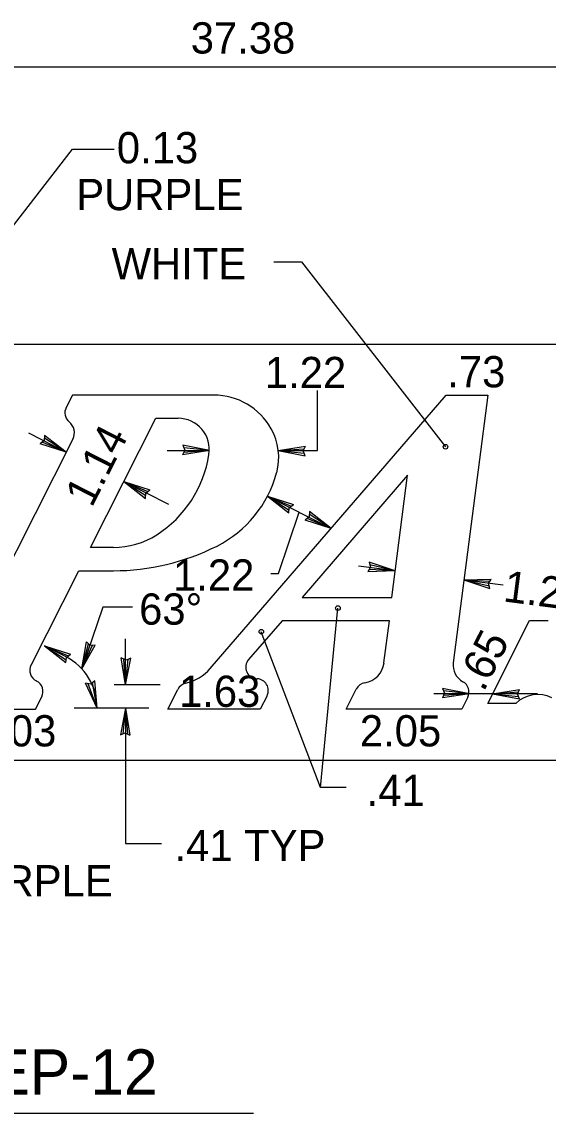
# Model space of a CAD drawing. Extents: x 10268197 to 10268826, y 2141503 to 2142677.
# Drawn here: x 10268799.84 to 10268809.85, y 2142357.53 to 2142378.29 of the extents above; entities that cross this region are included whole.
import ezdxf

# ---------------------------------------------------------------- set-up
doc = ezdxf.new("R2010")
doc.units = 0
for name, color, linetype in [('1', 7, 'Continuous'), ('21', 7, 'Continuous'), ('Default', 7, 'Continuous')]:
    doc.layers.add(name, color=color, linetype=linetype)

msp = doc.modelspace()

# ---------------------------------------------------------------- linework, layer by layer
at = {"layer": '1'}
for p, q in [((10268783.958, 2142377.436), (10268805.311, 2142377.436)), ((10268805.311, 2142377.436), (10268824.378, 2142377.436)), ((10268799.078, 2142373.645), (10268800.798, 2142375.868)), ((10268800.798, 2142375.868), (10268801.593, 2142375.868)), ((10268804.629, 2142373.722), (10268805.152, 2142373.722)), ((10268805.152, 2142373.722), (10268807.892, 2142370.208)), ((10268805.46, 2142370.136), (10268805.46, 2142371.278)), ((10268799.961, 2142370.47), (10268800.679, 2142370.104)), ((10268800.269, 2142370.424), (10268800.261, 2142370.326)), ((10268800.679, 2142370.104), (10268800.269, 2142370.424)), ((10268800.261, 2142370.326), (10268800.184, 2142370.264)), ((10268800.679, 2142370.104), (10268800.184, 2142370.264)), ((10268800.679, 2142370.104), (10268800.225, 2142370.297)), ((10268800.679, 2142370.104), (10268800.264, 2142370.373)), ((10268803.405, 2142370.136), (10268802.894, 2142370.235)), ((10268802.894, 2142370.235), (10268802.932, 2142370.144)), ((10268803.405, 2142370.136), (10268802.914, 2142370.187)), ((10268804.712, 2142370.136), (10268805.227, 2142370.217)), ((10268805.186, 2142370.128), (10268805.227, 2142370.217)), ((10268802.598, 2142370.136), (10268803.405, 2142370.136)), ((10268802.932, 2142370.144), (10268802.891, 2142370.054)), ((10268803.405, 2142370.136), (10268802.891, 2142370.054)), ((10268803.405, 2142370.136), (10268802.912, 2142370.101)), ((10268804.712, 2142370.136), (10268805.205, 2142370.17)), ((10268804.712, 2142370.136), (10268805.46, 2142370.136)), ((10268804.712, 2142370.136), (10268805.223, 2142370.037)), ((10268804.712, 2142370.136), (10268805.204, 2142370.085)), ((10268805.223, 2142370.037), (10268805.186, 2142370.128)), ((10268801.777, 2142369.546), (10268802.623, 2142369.114)), ((10268801.777, 2142369.546), (10268802.272, 2142369.385)), ((10268801.777, 2142369.546), (10268802.187, 2142369.225)), ((10268801.777, 2142369.546), (10268802.191, 2142369.277)), ((10268801.777, 2142369.546), (10268802.231, 2142369.353)), ((10268802.194, 2142369.324), (10268802.272, 2142369.385)), ((10268802.187, 2142369.225), (10268802.194, 2142369.324)), ((10268804.505, 2142369.27), (10268805.717, 2142368.652)), ((10268804.505, 2142369.27), (10268804.999, 2142369.109)), ((10268804.505, 2142369.27), (10268804.915, 2142368.95)), ((10268804.505, 2142369.27), (10268804.919, 2142369.002)), ((10268804.505, 2142369.27), (10268804.958, 2142369.077)), ((10268804.915, 2142368.95), (10268804.922, 2142369.048)), ((10268804.922, 2142369.048), (10268804.999, 2142369.109)), ((10268806.937, 2142367.846), (10268806.239, 2142367.937)), ((10268806.468, 2142367.915), (10268806.416, 2142367.831)), ((10268806.937, 2142367.846), (10268806.443, 2142368.01)), ((10268806.443, 2142368.01), (10268806.468, 2142367.915)), ((10268806.937, 2142367.846), (10268806.456, 2142367.96)), ((10268806.937, 2142367.846), (10268806.416, 2142367.831)), ((10268806.937, 2142367.846), (10268806.444, 2142367.875)), ((10268808.244, 2142367.677), (10268808.764, 2142367.691)), ((10268808.244, 2142367.677), (10268808.989, 2142367.58)), ((10268808.244, 2142367.677), (10268808.737, 2142367.512)), ((10268808.244, 2142367.677), (10268808.725, 2142367.563)), ((10268808.244, 2142367.677), (10268808.736, 2142367.648)), ((10268808.712, 2142367.608), (10268808.764, 2142367.691)), ((10268808.737, 2142367.512), (10268808.712, 2142367.608)), ((10268801.373, 2142367.159), (10268800.975, 2142365.984)), ((10268801.938, 2142367.159), (10268801.373, 2142367.159)), ((10268805.518, 2142363.728), (10268805.846, 2142367.139)), ((10268805.518, 2142363.728), (10268804.39, 2142366.69)), ((10268800.975, 2142365.984), (10268801.063, 2142366.496)), ((10268800.975, 2142365.984), (10268801.101, 2142366.461)), ((10268801.135, 2142366.429), (10268801.063, 2142366.496)), ((10268801.809, 2142365.676), (10268801.809, 2142366.555)), ((10268800.668, 2142366.215), (10268800.264, 2142366.422)), ((10268800.264, 2142366.422), (10268800.759, 2142366.26)), ((10268800.264, 2142366.422), (10268800.674, 2142366.101)), ((10268800.264, 2142366.422), (10268800.678, 2142366.153)), ((10268800.264, 2142366.422), (10268800.718, 2142366.229)), ((10268800.682, 2142366.199), (10268800.759, 2142366.26)), ((10268800.975, 2142365.984), (10268801.233, 2142366.435)), ((10268800.975, 2142365.984), (10268801.182, 2142366.432)), ((10268801.233, 2142366.435), (10268801.135, 2142366.429)), ((10268800.674, 2142366.101), (10268800.682, 2142366.199)), ((10268801.809, 2142365.676), (10268801.727, 2142366.19)), ((10268801.817, 2142366.15), (10268801.727, 2142366.19)), ((10268801.809, 2142365.676), (10268801.774, 2142366.168)), ((10268801.809, 2142365.676), (10268801.908, 2142366.187)), ((10268801.809, 2142365.676), (10268801.86, 2142366.167)), ((10268801.908, 2142366.187), (10268801.817, 2142366.15)), ((10268801.268, 2142365.237), (10268801.048, 2142365.709)), ((10268801.145, 2142365.694), (10268801.048, 2142365.709)), ((10268801.268, 2142365.237), (10268801.099, 2142365.701)), ((10268801.223, 2142365.755), (10268801.145, 2142365.694)), ((10268801.268, 2142365.237), (10268801.182, 2142365.723)), ((10268801.268, 2142365.237), (10268801.223, 2142365.755)), ((10268802.468, 2142365.676), (10268801.589, 2142365.676)), ((10268808.349, 2142365.511), (10268807.673, 2142365.511)), ((10268808.788, 2142365.511), (10268808.349, 2142365.511)), ((10268809.645, 2142365.511), (10268808.788, 2142365.511)), ((10268802.248, 2142365.237), (10268800.829, 2142365.237)), ((10268801.809, 2142365.237), (10268801.709, 2142364.726)), ((10268801.809, 2142365.237), (10268801.757, 2142364.746)), ((10268801.809, 2142365.237), (10268801.809, 2142362.659)), ((10268801.809, 2142365.237), (10268801.89, 2142364.723)), ((10268801.809, 2142365.237), (10268801.843, 2142364.745)), ((10268801.709, 2142364.726), (10268801.801, 2142364.764)), ((10268801.801, 2142364.764), (10268801.89, 2142364.723)), ((10268806.004, 2142363.728), (10268805.518, 2142363.728)), ((10268801.809, 2142362.659), (10268802.494, 2142362.659))]:
    msp.add_line(p, q, dxfattribs=at)
msp.add_lwpolyline([(10268804.569, 2142367.794), (10268804.717, 2142367.794), (10268805.111, 2142368.961)], dxfattribs=at)
for centre in [(10268807.892, 2142370.208), (10268805.846, 2142367.139), (10268804.39, 2142366.69)]:
    msp.add_circle(centre, 0.0439, dxfattribs=at)
msp.add_arc((10268800.169, 2142365.237), 1.098, 0, 62.9941, dxfattribs=at)
at = {"layer": '21'}
for p, q in [((10268805.306, 2142368.973), (10268805.298, 2142368.875)), ((10268805.717, 2142368.652), (10268805.306, 2142368.973)), ((10268805.298, 2142368.875), (10268805.221, 2142368.813)), ((10268805.717, 2142368.652), (10268805.221, 2142368.813)), ((10268805.717, 2142368.652), (10268805.262, 2142368.845)), ((10268805.717, 2142368.652), (10268805.302, 2142368.922)), ((10268807.875, 2142365.519), (10268807.834, 2142365.43)), ((10268808.349, 2142365.511), (10268807.834, 2142365.43)), ((10268808.349, 2142365.511), (10268807.838, 2142365.61)), ((10268807.838, 2142365.61), (10268807.875, 2142365.519)), ((10268808.349, 2142365.511), (10268807.856, 2142365.477)), ((10268808.349, 2142365.511), (10268807.857, 2142365.562)), ((10268808.788, 2142365.511), (10268809.303, 2142365.593)), ((10268808.788, 2142365.511), (10268809.281, 2142365.546)), ((10268808.788, 2142365.511), (10268809.3, 2142365.412)), ((10268808.788, 2142365.511), (10268809.28, 2142365.46)), ((10268809.262, 2142365.503), (10268809.303, 2142365.593)), ((10268809.3, 2142365.412), (10268809.262, 2142365.503)), ((10268794.399, 2142357.533), (10268804.24, 2142357.533))]:
    msp.add_line(p, q, dxfattribs=at)
at = {"layer": 'Default'}
for p, q in [((10268799.315, 2142372.157), (10268824.378, 2142372.157)), ((10268800.797, 2142371.19), (10268800.678, 2142370.954)), ((10268803.488, 2142371.19), (10268800.797, 2142371.19)), ((10268803.42, 2142365.991), (10268807.907, 2142371.19)), ((10268807.907, 2142371.19), (10268808.698, 2142371.19)), ((10268808.698, 2142371.19), (10268808.04, 2142366.097)), ((10268801.142, 2142368.291), (10268802.385, 2142370.748)), ((10268802.385, 2142370.748), (10268802.809, 2142370.748)), ((10268800.805, 2142370.354), (10268798.63, 2142366.052)), ((10268807.171, 2142369.664), (10268805.166, 2142367.339)), ((10268806.871, 2142367.339), (10268807.171, 2142369.664)), ((10268801.577, 2142368.291), (10268801.142, 2142368.291)), ((10268800.01, 2142366.053), (10268800.918, 2142367.849)), ((10268800.918, 2142367.849), (10268801.577, 2142367.849)), ((10268805.166, 2142367.339), (10268806.871, 2142367.339)), ((10268804.785, 2142366.897), (10268804.148, 2142366.159)), ((10268806.826, 2142366.897), (10268804.785, 2142366.897)), ((10268806.722, 2142366.097), (10268806.826, 2142366.897)), ((10268808.695, 2142365.326), (10268809.492, 2142366.904)), ((10268809.492, 2142366.904), (10268809.845, 2142366.904)), ((10268800.094, 2142365.215), (10268800.214, 2142365.452)), ((10268802.612, 2142365.215), (10268802.803, 2142365.593)), ((10268804.499, 2142365.471), (10268804.369, 2142365.215)), ((10268806.003, 2142365.215), (10268806.196, 2142365.599)), ((10268808.315, 2142365.443), (10268808.2, 2142365.215)), ((10268797.898, 2142365.215), (10268800.094, 2142365.215)), ((10268804.369, 2142365.215), (10268802.612, 2142365.215)), ((10268808.2, 2142365.215), (10268806.003, 2142365.215)), ((10268809.228, 2142365.326), (10268808.695, 2142365.326)), ((10268798.581, 2142364.248), (10268820.349, 2142364.248))]:
    msp.add_line(p, q, dxfattribs=at)
for centre, major_axis, start_param, end_param in [((10268803.488, 2142369.929), (0, 1.261), 5.226065, 6.283185), ((10268800.873, 2142370.854), (0, -0.221), 4.240773, 5.605302), ((10268800.57, 2142370.475), (0, -0.266), 1.099604, 2.46371), ((10268802.808, 2142370.151), (0, -0.598), 1.415043, 3.141593), ((10268803.622, 2142370.005), (0, 1.107), 4.445482, 5.226065), ((10268801.224, 2142370.401), (0, -2.213), 0.565847, 1.415043), ((10268802.562, 2142370.297), (0, -2.213), 0.465011, 1.30389), ((10268801.577, 2142369.841), (0, -1.549), 0, 0.565847), ((10268801.577, 2142372.275), (0, -4.426), 0, 0.465011), ((10268800.205, 2142365.953), (0, 0.221), 1.099355, 2.701477), ((10268804.313, 2142366.014), (0, 0.221), 0.854904, 3.118676), ((10268806.287, 2142366.154), (0, -0.443), 0.161263, 1.440999), ((10268808.388, 2142366.051), (0, 0.354), 1.441439, 2.650585), ((10268802.757, 2142366.573), (0, -0.885), 0.22194, 0.855152), ((10268800.018, 2142365.552), (0, 0.221), 4.241567, 5.84307), ((10268802.999, 2142365.493), (0, -0.221), 3.363532, 4.241567), ((10268804.303, 2142365.572), (0, 0.221), 4.240773, 6.260268), ((10268806.392, 2142365.499), (0, -0.221), 3.302856, 4.241567), ((10268808.119, 2142365.544), (0, 0.221), 4.240773, 5.792177), ((10268809.649, 2142364.874), (0, -0.62), 2.69443, 3.895387)]:
    msp.add_ellipse(centre, major_axis=major_axis, ratio=0.992614, start_param=start_param, end_param=end_param, dxfattribs=at)

# ---------------------------------------------------------------- texts
at = {"layer": '1'}
for s, height, p in [('37.38', 0.5942, (10268803.048, 2142377.686)), ('0.13', 0.5942, (10268801.642, 2142375.598)), ('PURPLE', 0.5942, (10268800.871, 2142374.707)), ('WHITE', 0.5942, (10268801.543, 2142373.392)), ('1.22', 0.5942, (10268804.457, 2142371.322)), ('.73', 0.5942, (10268807.926, 2142371.337)), ('63°', 0.5942, (10268802.066, 2142366.824)), ('1.63', 0.5942, (10268802.824, 2142365.26)), ('2.03', 0.5942, (10268798.944, 2142364.508)), ('2.05', 0.5942, (10268806.264, 2142364.508)), ('.41', 0.5942, (10268806.393, 2142363.376)), ('.41 TYP', 0.5942, (10268802.739, 2142362.326)), ('PURPLE', 0.5942, (10268798.384, 2142361.657)), ('LOGO EP-12', 0.8605, (10268795.575, 2142357.886))]:
    msp.add_text(s, height=height, dxfattribs=at).set_placement(p)
for s, rotation, p in [('1.14', 62.9907, (10268801.164, 2142369.033)), ('1.22', 360, (10268802.711, 2142367.471)), ('1.22', 352.5994, (10268808.975, 2142367.268)), ('.65', 63, (10268808.617, 2142365.53))]:
    msp.add_text(s, height=0.5942, rotation=rotation, dxfattribs=at).set_placement(p)

doc.saveas('drawing.dxf')
